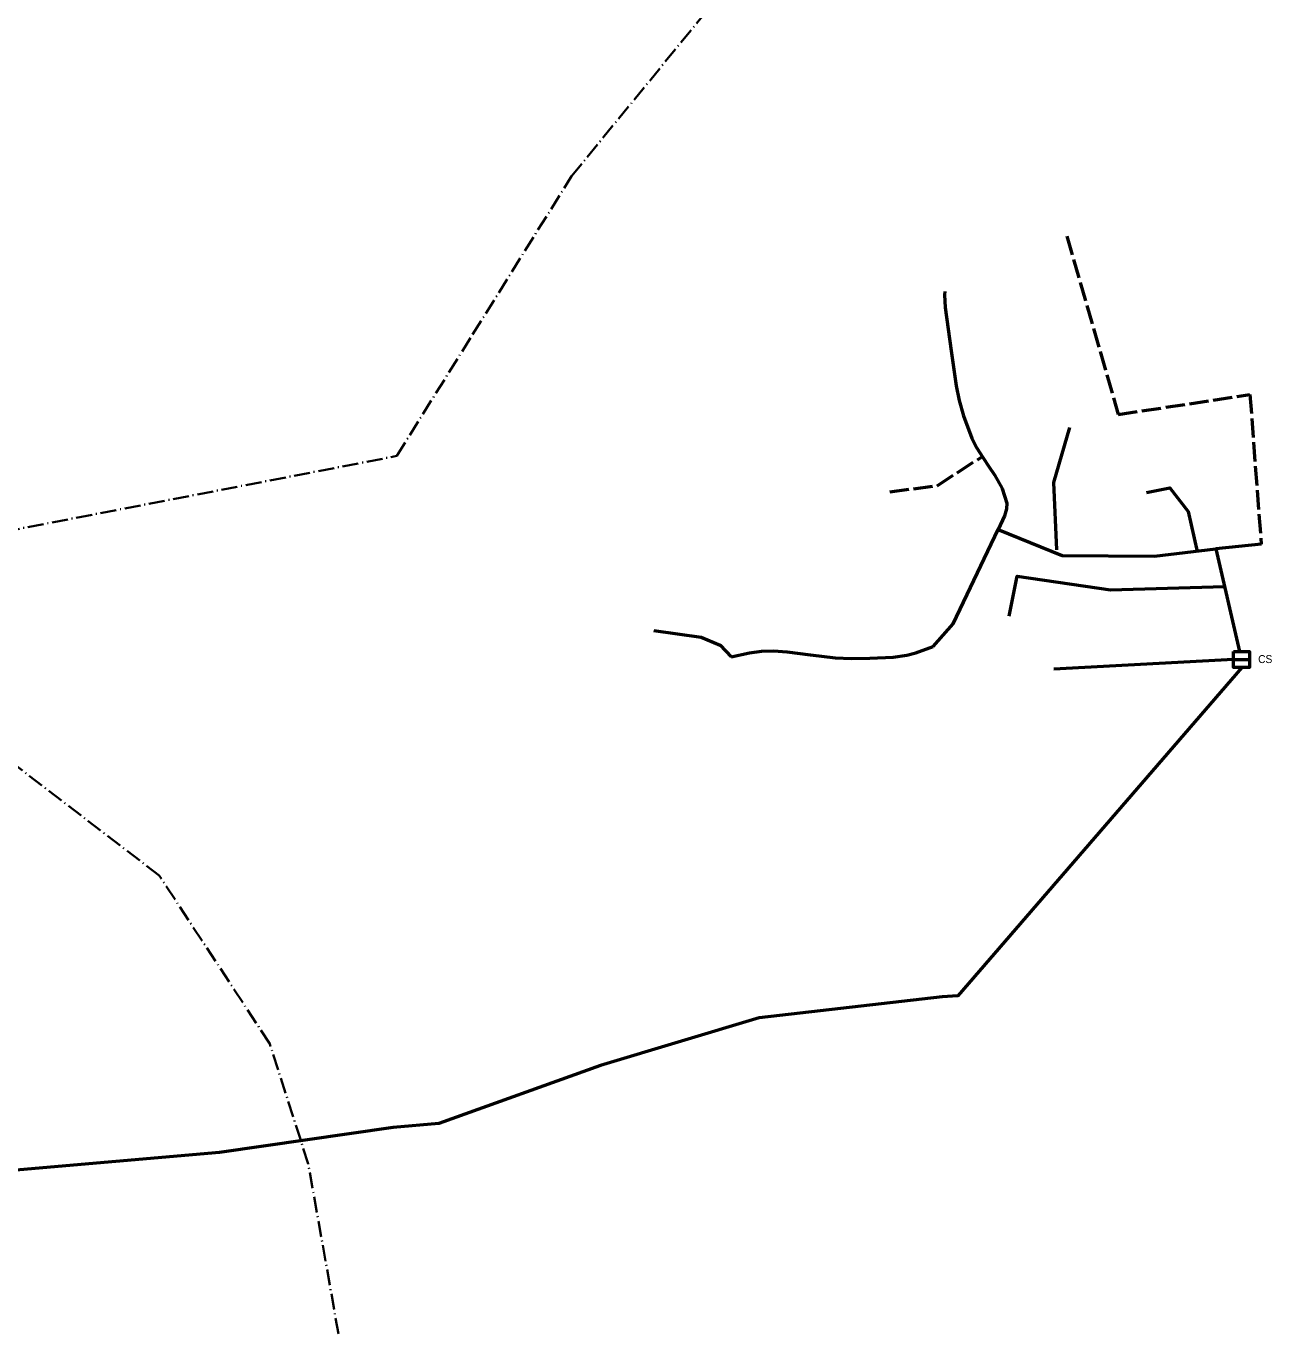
# Model space of a CAD drawing. Extents: x -650270 to -643402, y -1075206 to -1066724.
# Drawn here: x -644959 to -643402, y -1070961 to -1069326 of the extents above; entities that cross this region are included whole.
import ezdxf

# ---------------------------------------------------------------- set-up
doc = ezdxf.new("R2010")
doc.units = 0
doc.header["$LTSCALE"] = 4
doc.linetypes.add('DOT_DASHED', pattern=[7.7, 5, -1.2, 0.3, -1.2])
doc.linetypes.add('LONG_DASHED', pattern=[7.5, 6, -1.5])
for name, color, linetype, lineweight in [('17', 7, 'DOT_DASHED', 35), ('41', 7, 'Continuous', 25), ('48', 7, 'Continuous', 53), ('50', 7, 'Continuous', 53)]:
    doc.layers.add(name, color=color, linetype=linetype, lineweight=lineweight)
doc.layers.add('42', color=7, linetype='Continuous')

msp = doc.modelspace()

# ---------------------------------------------------------------- linework, layer by layer
at = {"layer": '17'}
for points in [[(-644568.435, -1070960.552), (-644606.234, -1070747.935), (-644654.246, -1070597.895), (-644792.283, -1070387.84), (-645046.599, -1070192.79), (-645228.623, -1070004.752), (-645232.28, -1069980.924), (-645262.713, -1069836.388), (-645315.002, -1069657.333), (-645409.031, -1069473.75), (-645471.738, -1069397.026), (-645547.224, -1069323.801), (-645594.94, -1069288.511), (-645620.197, -1069220.915), (-645784.301, -1069029.743), (-645967.439, -1068809.81), (-646082.481, -1068583.109), (-646148.037, -1068369.943), (-646184.835, -1068097.563), (-646183.288, -1067867.427)], [(-645228.623, -1070004.752), (-644495.665, -1069863.346), (-644400.764, -1069711.504), (-644277.073, -1069513.597), (-644078.1, -1069270.213), (-644047.301, -1069043.419)]]:
    msp.add_lwpolyline(points, dxfattribs=at)
at = {"layer": '41', "lineweight": 53}
msp.add_line((-643450.027, -1070117.812), (-643430.027, -1070117.812), dxfattribs=at)
msp.add_lwpolyline([(-643450.027, -1070107.812), (-643430.027, -1070107.812), (-643430.027, -1070127.812), (-643450.027, -1070127.812)], close=True, dxfattribs=at)
at = {"layer": '48', "linetype": 'LONG_DASHED'}
msp.add_line((-643658.395, -1069588.818), (-643594.181, -1069811.599), dxfattribs=at)
at = {"layer": '48'}
for p, q in [((-643415.602, -1069973.457), (-643472.434, -1069979.54)), ((-643674.528, -1070129.34), (-643450.027, -1070117.352))]:
    msp.add_line(p, q, dxfattribs=at)
for points in [[(-643810.627, -1069657.665), (-643811.385, -1069662.021), (-643810.389, -1069677.722), (-643802.82, -1069731.886), (-643796.749, -1069775.852), (-643792.823, -1069793.926), (-643787.529, -1069813.369), (-643777.123, -1069840.937), (-643771.098, -1069852.895), (-643763.019, -1069865.538), (-643755.762, -1069876.675), (-643748.825, -1069886.853), (-643739.057, -1069904.105), (-643733.398, -1069922.453), (-643733.672, -1069929.3), (-643736.136, -1069938.154), (-643744.205, -1069955.268)], [(-643655.213, -1069827.906), (-643674.851, -1069896.398), (-643671.436, -1069980.856)], [(-643558.728, -1069909.08), (-643529.51, -1069903.099), (-643506.883, -1069932.918), (-643495.544, -1069982.565)], [(-643825.501, -1070101.354), (-643800.43, -1070073.069), (-643744.205, -1069955.268)], [(-643744.205, -1069955.268), (-643664.391, -1069987.784), (-643548.771, -1069988.527), (-643472.434, -1069979.54), (-643442.585, -1070107.812)], [(-643730.467, -1070063.614), (-643720.412, -1070013.703), (-643603.827, -1070030.469), (-643461.54, -1070026.354)], [(-644174.372, -1070081.528), (-644115.344, -1070090.018), (-644091.49, -1070099.721), (-644077.983, -1070114.354)], [(-644077.983, -1070114.354), (-644054.663, -1070109.432), (-644040.027, -1070107.201), (-644024.686, -1070106.729), (-644007.981, -1070107.962), (-643978.816, -1070112.024), (-643947.688, -1070115.858), (-643927.411, -1070116.568), (-643904.548, -1070116.112), (-643875.543, -1070114.925), (-643858.108, -1070112.46), (-643846.88, -1070109.266), (-643825.501, -1070101.354)]]:
    msp.add_lwpolyline(points, dxfattribs=at)
at = {"layer": '48', "linetype": 'LONG_DASHED'}
for points in [[(-643594.181, -1069811.599), (-643429.636, -1069786.459), (-643415.602, -1069973.457)], [(-643879.717, -1069908.04), (-643820.566, -1069900.574), (-643763.713, -1069863.82)]]:
    msp.add_lwpolyline(points, dxfattribs=at)
at = {"layer": '50'}
msp.add_lwpolyline([(-643439.868, -1070127.812), (-643794.576, -1070538.041), (-643814.314, -1070539.274), (-644042.664, -1070565.642), (-644241.161, -1070625.072), (-644443.224, -1070697.577), (-644500.038, -1070702.585), (-644716.965, -1070734.034), (-644976.129, -1070756.486), (-645086.887, -1070754.876), (-645202.78, -1070753.267), (-645305.795, -1070754.34), (-645369.783, -1070785.657), (-645445.374, -1070804.496)], dxfattribs=at)

# ---------------------------------------------------------------- texts
at = {"layer": '42', "width": 0.95}
msp.add_text('CS', height=10, dxfattribs=at).set_placement((-643419.321, -1070122.194))

doc.saveas('drawing.dxf')
